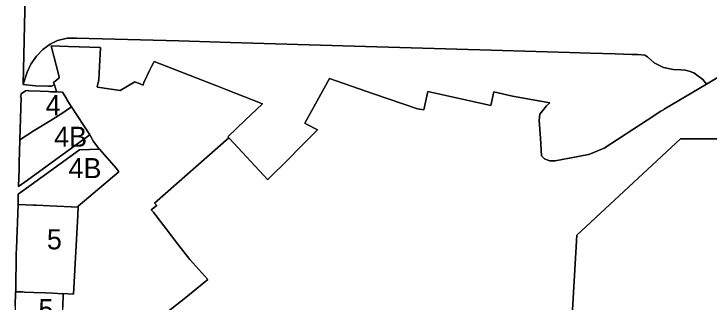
# Model space of a CAD drawing. Extents: x 598968 to 613553, y 4409678 to 4430833.
# Drawn here: x 607715.3 to 608130.3, y 4415273.1 to 4415445.3 of the extents above; entities that cross this region are included whole.
import ezdxf

# ---------------------------------------------------------------- set-up
doc = ezdxf.new("R2010")
doc.units = 0
for name, color, linetype in [('1', 7, 'Continuous'), ('SUBZONA 4B. Cases bifamiliars', 7, 'Continuous'), ('Sòl Rústic Comú', 7, 'Continuous'), ('ZONA 4. CASES UNIFAMILIRAS AÏLLADES EN PARCEL.LES', 7, 'Continuous'), ('ZONA 5. CASES UNIFAMILIARS EN RENGLE', 7, 'Continuous')]:
    doc.layers.add(name, color=color, linetype=linetype)

msp = doc.modelspace()

# ---------------------------------------------------------------- linework, layer by layer
at = {"layer": '1'}
for points in [[(607716.0004, 4415270.9949), (607716.2418, 4415278.7576), (607716.2604, 4415279.3548), (607716.3084, 4415279.353), (607716.3058, 4415279.384), (607716.4671, 4415287.367), (607716.6414, 4415294.9014), (607716.7003, 4415302.7647), (607716.7203, 4415304.3546), (607716.9703, 4415310.8846), (607717.1902, 4415315.6945), (607717.3488, 4415320.4994), (607717.542, 4415326.3498), (607717.7441, 4415331.4722), (607717.8371, 4415337.5872), (607725.5373, 4415343.1423), (607725.54, 4415343.1443), (607754.3284, 4415364.1674), (607766.4119, 4415364.4796), (607766.0292, 4415364.9179), (607762.822, 4415368.9888), (607760.6183, 4415373.0128), (607760.5982, 4415373.0433), (607735.9723, 4415355.1678), (607735.1685, 4415354.5843), (607723.4234, 4415346.0588), (607717.9786, 4415342.1065), (607718.3101, 4415352.6441), (607718.4123, 4415356.2764), (607718.8, 4415370.0539), (607719.4999, 4415395.5236), (607719.2099, 4415395.5736), (607719.5557, 4415397.138), (607719.6299, 4415397.4736), (607722.2499, 4415399.3936), (607724.0799, 4415399.4837), (607724.0899, 4415399.3237), (607730.8522, 4415399.0657), (607735.8935, 4415398.8733), (607737.2108, 4415398.823), (607740.7749, 4415398.6871), (607740.7245, 4415398.8811), (607739.4304, 4415402.8938), (607739.3309, 4415402.8553), (607737.7109, 4415402.1853), (607735.5009, 4415402.1052), (607728.151, 4415402.2551), (607720.8462, 4415403.14), (607723.2095, 4415509.3223)], [(607723.2095, 4415509.3223), (607720.8462, 4415403.14), (607721.3472, 4415405.1109), (607723.1007, 4415410.4916), (607725.3897, 4415415.2877), (607728.6901, 4415419.9419), (607732.5134, 4415424.0215), (607736.8838, 4415427.2346), (607741.3716, 4415429.3648), (607747.0739, 4415430.7497), (607752.5899, 4415430.8702), (607813.6487, 4415429.2097), (607844.5152, 4415428.1033), (607918.4332, 4415426.0817), (608006.9027, 4415423.4662), (608047.0068, 4415422.3157), (608059.3667, 4415421.9209), (608074.1537, 4415421.4063), (608084.1836, 4415421.0501), (608087.6367, 4415420.9714), (608091.9301, 4415420.7138), (608093.5162, 4415419.6223), (608097.569, 4415416.1014), (608102.9611, 4415413.3552), (608108.7557, 4415412.0832), (608113.3021, 4415411.8369), (608115.9805, 4415411.5905), (608118.3769, 4415411.168), (608121.1962, 4415410.0414), (608126.4536, 4415406.0877), (608128.7456, 4415403.3263), (608137.7552, 4415408.678)], [(607785.4192, 4415250.3529), (607817.8787, 4415275.7844), (607831.0679, 4415286.6738), (607820.2127, 4415298.6709), (607813.203, 4415307.7641), (607806.1933, 4415316.8572), (607801.4386, 4415323.0452), (607798.4984, 4415326.8717), (607798.2184, 4415327.1753), (607797.2458, 4415328.2297), (607800.5082, 4415330.867), (607799.2384, 4415332.2116), (607843.5032, 4415371.3059), (607843.5324, 4415371.3317), (607842.9649, 4415371.9447), (607853.4032, 4415381.8467), (607863.642, 4415391.5597), (607842.2922, 4415399.9421), (607836.424, 4415402.2462), (607834.763, 4415402.8982), (607799.0601, 4415416.9162), (607798.638, 4415416.1149), (607797.4258, 4415413.814), (607796.2102, 4415411.5062), (607792.899, 4415404.3359), (607792.4203, 4415402.7322), (607791.0026, 4415403.2717), (607789.591, 4415403.809), (607788.7388, 4415404.1334), (607787.4703, 4415404.6161), (607778.7547, 4415399.4528), (607765.1609, 4415401.5446), (607765.1806, 4415401.6226), (607764.889, 4415401.6675), (607765.9674, 4415405.9432), (607766.4203, 4415413.8013), (607766.9927, 4415424.9962), (607766.9985, 4415425.1082), (607747.8341, 4415425.8419), (607737.5092, 4415426.2372), (607742.0013, 4415408.494), (607742.3587, 4415407.0824), (607742.3418, 4415407.0687), (607740.6672, 4415405.708), (607738.9681, 4415404.3273), (607739.3012, 4415403.2943), (607739.4304, 4415402.8938), (607740.7245, 4415398.8811), (607740.7749, 4415398.6871), (607743.9996, 4415398.564), (607744.2993, 4415398.4735), (607746.5594, 4415394.6794), (607746.9373, 4415394.0582), (607749.4192, 4415389.9784), (607749.6093, 4415389.6904), (607760.5982, 4415373.0433), (607760.6183, 4415373.0128), (607762.822, 4415368.9888), (607766.0292, 4415364.9179), (607766.4119, 4415364.4796), (607776.4641, 4415352.9657), (607777.9887, 4415350.9605), (607753.6294, 4415330.39), (607753.6063, 4415329.9426), (607753.3506, 4415324.9981), (607750.9099, 4415277.801), (607744.3246, 4415278.2889), (607744.3195, 4415278.101), (607744.6, 4415278.0854), (607744.5992, 4415278.054), (607744.4101, 4415270.1954)]]:
    msp.add_lwpolyline(points, dxfattribs=at)
msp.add_lwpolyline([(608128.7456, 4415403.3263), (608126.4536, 4415406.0877), (608121.1962, 4415410.0414), (608118.3769, 4415411.168), (608115.9805, 4415411.5905), (608113.3021, 4415411.8369), (608108.7557, 4415412.0832), (608102.9611, 4415413.3552), (608097.569, 4415416.1014), (608093.5162, 4415419.6223), (608091.9301, 4415420.7138), (608087.6367, 4415420.9714), (608084.1836, 4415421.0501), (608074.1537, 4415421.4063), (608059.3667, 4415421.9209), (608047.0068, 4415422.3157), (608006.9027, 4415423.4662), (607918.4332, 4415426.0817), (607844.5152, 4415428.1033), (607813.6487, 4415429.2097), (607752.5899, 4415430.8702), (607747.0739, 4415430.7497), (607741.3716, 4415429.3648), (607736.8838, 4415427.2346), (607732.5134, 4415424.0215), (607728.6901, 4415419.9419), (607725.3897, 4415415.2877), (607723.1007, 4415410.4916), (607721.3472, 4415405.1109), (607720.8462, 4415403.14), (607728.151, 4415402.2551), (607735.5009, 4415402.1052), (607737.7109, 4415402.1853), (607739.3309, 4415402.8553), (607739.4304, 4415402.8938), (607739.3012, 4415403.2943), (607738.9681, 4415404.3273), (607740.6672, 4415405.708), (607742.3418, 4415407.0687), (607742.3587, 4415407.0824), (607742.0013, 4415408.494), (607737.5092, 4415426.2372), (607747.8341, 4415425.8419), (607766.9985, 4415425.1082), (607766.9927, 4415424.9962), (607766.4203, 4415413.8013), (607765.9674, 4415405.9432), (607764.889, 4415401.6675), (607765.1806, 4415401.6226), (607765.1609, 4415401.5446), (607778.7547, 4415399.4528), (607787.4703, 4415404.6161), (607788.7388, 4415404.1334), (607789.591, 4415403.809), (607791.0026, 4415403.2717), (607792.4203, 4415402.7322), (607792.899, 4415404.3359), (607796.2102, 4415411.5062), (607797.4258, 4415413.814), (607798.638, 4415416.1149), (607799.0601, 4415416.9162), (607834.763, 4415402.8982), (607836.424, 4415402.2462), (607842.2922, 4415399.9421), (607863.642, 4415391.5597), (607853.4032, 4415381.8467), (607842.9649, 4415371.9447), (607843.5324, 4415371.3317), (607843.7524, 4415371.0945), (607844.0234, 4415370.8016), (607866.8082, 4415346.176), (607866.8702, 4415346.2385), (607866.8894, 4415346.2579), (607866.9328, 4415346.3016), (607879.4941, 4415358.9734), (607885.1763, 4415364.7054), (607896.4048, 4415376.0325), (607896.4353, 4415376.0633), (607896.4658, 4415376.0941), (607889.9836, 4415379.4267), (607889.6177, 4415379.6148), (607889.2857, 4415379.7855), (607888.9537, 4415379.9561), (607903.6254, 4415406.6336), (607929.9448, 4415397.6248), (607956.2642, 4415388.616), (607959.8841, 4415387.8962), (607962.2723, 4415399.0147), (607999.9013, 4415390.6418), (608001.8131, 4415398.7974), (608012.9128, 4415396.1879), (608035.2074, 4415392.1628), (608035.1344, 4415392.0977), (608035.0652, 4415392.0359), (608034.9229, 4415391.9089), (608033.2457, 4415390.4124), (608029.2424, 4415385.4288), (608028.8677, 4415381.6079), (608029.5402, 4415371.0737), (608030.2126, 4415360.5394), (608031.9876, 4415358.6995), (608032.1575, 4415358.6389), (608032.218, 4415358.6173), (608032.3276, 4415358.5782), (608035.2275, 4415357.5446), (608038.4424, 4415357.5798), (608046.6949, 4415359.145), (608046.8986, 4415359.1814), (608058.252, 4415361.2104), (608058.4074, 4415361.2746), (608067.5668, 4415365.0606), (608093.2641, 4415381.7823), (608101.511, 4415387.1488), (608103.0393, 4415388.0565), (608103.4737, 4415388.3146)], close=True, dxfattribs=at)
at = {"layer": 'SUBZONA 4B. Cases bifamiliars'}
for points in [[(607760.5982, 4415373.0433), (607749.6093, 4415389.6904), (607743.3297, 4415385.3142), (607736.8055, 4415381.3122), (607727.4067, 4415375.5469), (607718.8, 4415370.0539), (607718.4123, 4415356.2764), (607718.3101, 4415352.6441), (607717.9786, 4415342.1065), (607723.4234, 4415346.0588), (607735.1685, 4415354.5843), (607735.9723, 4415355.1678)], [(607753.6063, 4415329.9426), (607753.6294, 4415330.39), (607777.9887, 4415350.9605), (607776.4641, 4415352.9657), (607766.4119, 4415364.4796), (607754.3284, 4415364.1674), (607725.54, 4415343.1443), (607725.5373, 4415343.1423), (607717.8371, 4415337.5872), (607717.7441, 4415331.4722), (607726.9092, 4415331.0551), (607728.5536, 4415330.989), (607736.6883, 4415330.6625), (607753.5237, 4415329.873)]]:
    msp.add_lwpolyline(points, close=True, dxfattribs=at)
at = {"layer": 'Sòl Rústic Comú'}
for points in [[(608137.7552, 4415408.678), (608128.7456, 4415403.3263), (608103.4737, 4415388.3146), (608103.0393, 4415388.0565), (608101.511, 4415387.1488), (608093.2641, 4415381.7823), (608067.5668, 4415365.0606), (608058.4074, 4415361.2746), (608058.252, 4415361.2104), (608046.8986, 4415359.1814), (608046.6949, 4415359.145), (608038.4424, 4415357.5798), (608035.2275, 4415357.5446), (608032.3276, 4415358.5782), (608032.218, 4415358.6173), (608032.1575, 4415358.6389), (608031.9876, 4415358.6995), (608030.2126, 4415360.5394), (608029.5402, 4415371.0737), (608028.8677, 4415381.6079), (608029.2424, 4415385.4288), (608033.2457, 4415390.4124), (608034.9229, 4415391.9089), (608035.0652, 4415392.0359), (608035.1344, 4415392.0977), (608035.2074, 4415392.1628), (608012.9128, 4415396.1879), (608001.8131, 4415398.7974), (607999.9013, 4415390.6418), (607962.2723, 4415399.0147), (607959.8841, 4415387.8962), (607956.2642, 4415388.616), (607929.9448, 4415397.6248), (607903.6254, 4415406.6336), (607888.9537, 4415379.9561), (607889.2857, 4415379.7855), (607889.6177, 4415379.6148), (607889.9836, 4415379.4267), (607896.4658, 4415376.0941), (607896.4353, 4415376.0633), (607896.4048, 4415376.0325), (607885.1763, 4415364.7054), (607879.4941, 4415358.9734), (607866.9328, 4415346.3016), (607866.8894, 4415346.2579), (607866.8702, 4415346.2385), (607866.8082, 4415346.176), (607844.0234, 4415370.8016), (607843.7524, 4415371.0945), (607843.5324, 4415371.3317), (607843.5032, 4415371.3059), (607799.2384, 4415332.2116), (607800.5082, 4415330.867), (607797.2458, 4415328.2297), (607798.2184, 4415327.1753), (607798.4984, 4415326.8717), (607801.4386, 4415323.0452), (607806.1933, 4415316.8572), (607813.203, 4415307.7641), (607820.2127, 4415298.6709), (607831.0679, 4415286.6738), (607817.8787, 4415275.7844), (607785.4192, 4415250.3529)], [(608041.8905, 4415151.858), (608051.3817, 4415313.1964), (608113.2577, 4415370.6966), (608147.1329, 4415370.6966), (608165.9455, 4415329.1966), (608170.5081, 4415317.1966), (608175.3081, 4415288.2708), (608175.3205, 4415288.1966), (608167.8201, 4415222.1966)], [(608167.8201, 4415222.1966), (608175.3205, 4415288.1966), (608175.3081, 4415288.2708), (608170.5081, 4415317.1966), (608165.9455, 4415329.1966), (608147.1329, 4415370.6966), (608113.2577, 4415370.6966), (608051.3817, 4415313.1964), (608041.8905, 4415151.858)]]:
    msp.add_lwpolyline(points, dxfattribs=at)
at = {"layer": 'ZONA 4. CASES UNIFAMILIRAS AÏLLADES EN PARCEL.LES'}
msp.add_lwpolyline([(607740.7749, 4415398.6871), (607737.2108, 4415398.823), (607735.8935, 4415398.8733), (607730.8522, 4415399.0657), (607724.0899, 4415399.3237), (607724.0799, 4415399.4837), (607722.2499, 4415399.3936), (607719.6299, 4415397.4736), (607719.5557, 4415397.138), (607719.2099, 4415395.5736), (607719.4999, 4415395.5236), (607718.8, 4415370.0539), (607727.4067, 4415375.5469), (607736.8055, 4415381.3122), (607743.3297, 4415385.3142), (607749.6093, 4415389.6904), (607749.4192, 4415389.9784), (607746.9373, 4415394.0582), (607746.5594, 4415394.6794), (607744.2993, 4415398.4735), (607743.9996, 4415398.564)], close=True, dxfattribs=at)
at = {"layer": 'ZONA 5. CASES UNIFAMILIARS EN RENGLE'}
for points in [[(607753.6063, 4415329.9426), (607753.5237, 4415329.873), (607736.6883, 4415330.6625), (607728.5536, 4415330.989), (607726.9092, 4415331.0551), (607717.7441, 4415331.4722), (607717.542, 4415326.3498), (607717.3488, 4415320.4994), (607717.1902, 4415315.6945), (607716.9703, 4415310.8846), (607716.7203, 4415304.3546), (607716.7003, 4415302.7647), (607716.6414, 4415294.9014), (607716.4671, 4415287.367), (607716.3058, 4415279.384), (607716.3084, 4415279.353), (607720.3971, 4415279.1943), (607721.6703, 4415279.1449), (607727.1532, 4415278.935), (607734.2002, 4415278.6652), (607738.7169, 4415278.4133), (607744.3195, 4415278.101), (607744.3246, 4415278.2889), (607750.9099, 4415277.801), (607753.3506, 4415324.9981)], [(607716.3084, 4415279.353), (607716.2604, 4415279.3548), (607716.2418, 4415278.7576), (607716.0004, 4415270.9949), (607715.7704, 4415263.445), (607715.4932, 4415255.1651), (607715.2505, 4415247.3752), (607721.5404, 4415247.2053), (607729.4103, 4415246.9454), (607735.8257, 4415246.727), (607743.4584, 4415246.4865), (607743.8001, 4415246.4757), (607744.0101, 4415254.4256), (607744.2301, 4415262.5955), (607744.4101, 4415270.1954), (607744.5992, 4415278.054), (607744.6, 4415278.0854), (607744.3195, 4415278.101), (607738.7169, 4415278.4133), (607734.2002, 4415278.6652), (607727.1532, 4415278.935), (607721.6703, 4415279.1449), (607720.3971, 4415279.1943)]]:
    msp.add_lwpolyline(points, close=True, dxfattribs=at)

# ---------------------------------------------------------------- texts
at = {"layer": 'SUBZONA 4B. Cases bifamiliars'}
for p in [(607739.2884, 4415365.8985), (607747.8664, 4415347.1763)]:
    msp.add_text('4B', height=12, dxfattribs=at).set_placement(p)
at = {"layer": 'ZONA 4. CASES UNIFAMILIRAS AÏLLADES EN PARCEL.LES'}
msp.add_text('4', height=12, dxfattribs=at).set_placement((607734.2046, 4415384.7688))
at = {"layer": 'ZONA 5. CASES UNIFAMILIARS EN RENGLE'}
for p in [(607734.9561, 4415304.6366), (607729.9252, 4415262.9153)]:
    msp.add_text('5', height=12, dxfattribs=at).set_placement(p)

doc.saveas('drawing.dxf')
